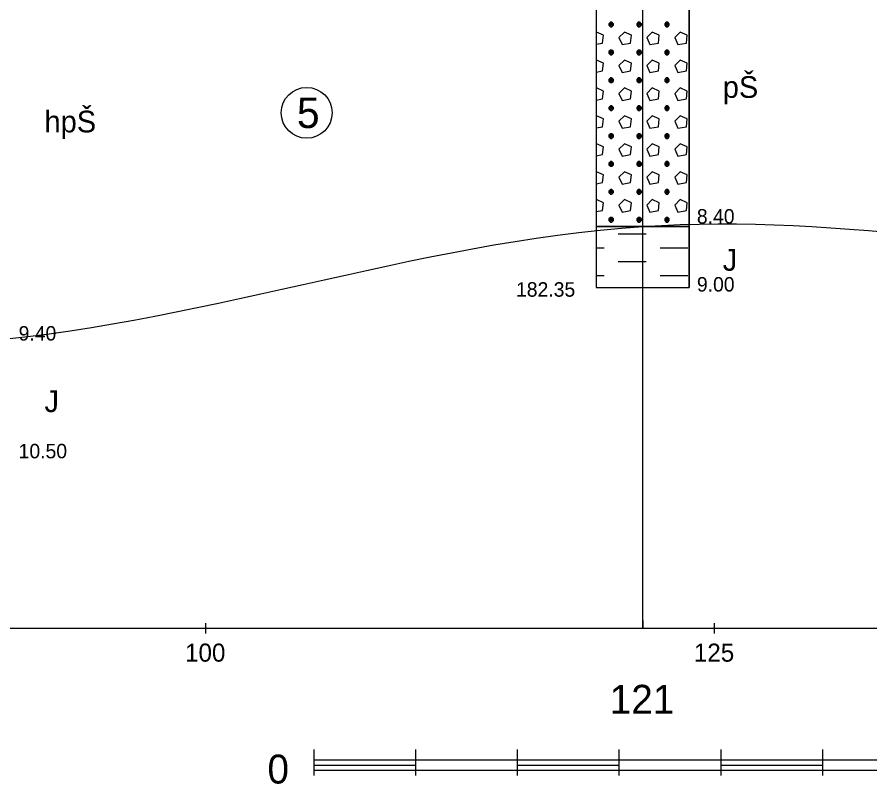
# Model space of a CAD drawing. Extents: x 3042 to 4120, y 576 to 2694.
# Drawn here: x 3345.86 to 3387.77, y 1544.18 to 1581.88 of the extents above; entities that cross this region are included whole.
import ezdxf

# ---------------------------------------------------------------- set-up
doc = ezdxf.new("R2010")
doc.units = 0
for name, color, linetype in [('14', 7, 'Continuous'), ('17', 7, 'Continuous'), ('18', 7, 'Continuous'), ('51', 7, 'Continuous'), ('52', 7, 'Continuous'), ('53', 7, 'Continuous'), ('56', 7, 'Continuous'), ('7', 7, 'Continuous'), ('8', 7, 'Continuous'), ('pomocna', 7, 'Continuous'), ('rozhraní', 7, 'Continuous')]:
    doc.layers.add(name, color=color, linetype=linetype)

msp = doc.modelspace()

# ---------------------------------------------------------------- linework, layer by layer
at = {"layer": '18'}
for p, q in [((3376.218, 1568.586), (3376.98, 1568.586)), ((3376.599, 1568.967), (3376.599, 1568.205)), ((3376.599, 1567.217), (3376.599, 1566.836)), ((3376.602, 1552.219), (3376.602, 1551.838))]:
    msp.add_line(p, q, dxfattribs=at)
at = {"layer": '51'}
for points in [[(3374.313, 1571.586), (3378.885, 1571.586), (3378.885, 1585.586), (3374.313, 1585.586)], [(3374.313, 1568.586), (3378.885, 1568.586), (3378.885, 1571.586), (3374.313, 1571.586)]]:
    msp.add_lwpolyline(points, close=True, dxfattribs=at)
for points in [[(3375.015, 1581.631), (3374.939, 1581.555), (3374.939, 1581.479), (3375.015, 1581.403), (3375.091, 1581.403), (3375.168, 1581.479), (3375.168, 1581.555), (3375.091, 1581.631), (3375.015, 1581.631), (3375.168, 1581.479), (3374.939, 1581.479), (3375.091, 1581.631)], [(3375.053, 1581.403), (3375.053, 1581.631)], [(3376.387, 1581.631), (3376.311, 1581.555), (3376.311, 1581.479), (3376.387, 1581.403), (3376.463, 1581.403), (3376.539, 1581.479), (3376.539, 1581.555), (3376.463, 1581.631), (3376.387, 1581.631), (3376.539, 1581.479), (3376.311, 1581.479), (3376.463, 1581.631)], [(3376.425, 1581.403), (3376.425, 1581.631)], [(3377.758, 1581.631), (3377.682, 1581.555), (3377.682, 1581.479), (3377.758, 1581.403), (3377.835, 1581.403), (3377.911, 1581.479), (3377.911, 1581.555), (3377.835, 1581.631), (3377.758, 1581.631), (3377.911, 1581.479), (3377.682, 1581.479), (3377.835, 1581.631)], [(3377.796, 1581.403), (3377.796, 1581.631)], [(3374.313, 1580.544), (3374.634, 1580.603), (3374.672, 1580.984), (3374.329, 1581.136), (3374.313, 1581.12)], [(3375.434, 1580.869), (3375.587, 1580.526), (3376.006, 1580.603), (3376.044, 1580.984), (3375.701, 1581.136), (3375.434, 1580.869)], [(3376.806, 1580.869), (3376.958, 1580.526), (3377.377, 1580.603), (3377.415, 1580.984), (3377.073, 1581.136), (3376.806, 1580.869)], [(3378.177, 1580.869), (3378.33, 1580.526), (3378.749, 1580.603), (3378.787, 1580.984), (3378.444, 1581.136), (3378.177, 1580.869)], [(3375.015, 1580.26), (3374.939, 1580.184), (3374.939, 1580.107), (3375.015, 1580.031), (3375.091, 1580.031), (3375.168, 1580.107), (3375.168, 1580.184), (3375.091, 1580.26), (3375.015, 1580.26), (3375.168, 1580.107), (3374.939, 1580.107), (3375.091, 1580.26)], [(3375.053, 1580.031), (3375.053, 1580.26)], [(3376.387, 1580.26), (3376.311, 1580.184), (3376.311, 1580.107), (3376.387, 1580.031), (3376.463, 1580.031), (3376.539, 1580.107), (3376.539, 1580.184), (3376.463, 1580.26), (3376.387, 1580.26), (3376.539, 1580.107), (3376.311, 1580.107), (3376.463, 1580.26)], [(3376.425, 1580.031), (3376.425, 1580.26)], [(3377.758, 1580.26), (3377.682, 1580.184), (3377.682, 1580.107), (3377.758, 1580.031), (3377.835, 1580.031), (3377.911, 1580.107), (3377.911, 1580.184), (3377.835, 1580.26), (3377.758, 1580.26), (3377.911, 1580.107), (3377.682, 1580.107), (3377.835, 1580.26)], [(3377.796, 1580.031), (3377.796, 1580.26)], [(3374.313, 1579.173), (3374.634, 1579.231), (3374.672, 1579.612), (3374.329, 1579.764), (3374.313, 1579.748)], [(3375.434, 1579.498), (3375.587, 1579.155), (3376.006, 1579.231), (3376.044, 1579.612), (3375.701, 1579.764), (3375.434, 1579.498)], [(3376.806, 1579.498), (3376.958, 1579.155), (3377.377, 1579.231), (3377.415, 1579.612), (3377.073, 1579.764), (3376.806, 1579.498)], [(3378.177, 1579.498), (3378.33, 1579.155), (3378.749, 1579.231), (3378.787, 1579.612), (3378.444, 1579.764), (3378.177, 1579.498)], [(3375.015, 1578.888), (3374.939, 1578.812), (3374.939, 1578.736), (3375.015, 1578.66), (3375.091, 1578.66), (3375.168, 1578.736), (3375.168, 1578.812), (3375.091, 1578.888), (3375.015, 1578.888), (3375.168, 1578.736), (3374.939, 1578.736), (3375.091, 1578.888)], [(3375.053, 1578.66), (3375.053, 1578.888)], [(3376.387, 1578.888), (3376.311, 1578.812), (3376.311, 1578.736), (3376.387, 1578.66), (3376.463, 1578.66), (3376.539, 1578.736), (3376.539, 1578.812), (3376.463, 1578.888), (3376.387, 1578.888), (3376.539, 1578.736), (3376.311, 1578.736), (3376.463, 1578.888)], [(3376.425, 1578.66), (3376.425, 1578.888)], [(3377.758, 1578.888), (3377.682, 1578.812), (3377.682, 1578.736), (3377.758, 1578.66), (3377.835, 1578.66), (3377.911, 1578.736), (3377.911, 1578.812), (3377.835, 1578.888), (3377.758, 1578.888), (3377.911, 1578.736), (3377.682, 1578.736), (3377.835, 1578.888)], [(3377.796, 1578.66), (3377.796, 1578.888)], [(3374.313, 1577.801), (3374.634, 1577.859), (3374.672, 1578.24), (3374.329, 1578.393), (3374.313, 1578.377)], [(3375.434, 1578.126), (3375.587, 1577.783), (3376.006, 1577.859), (3376.044, 1578.24), (3375.701, 1578.393), (3375.434, 1578.126)], [(3376.806, 1578.126), (3376.958, 1577.783), (3377.377, 1577.859), (3377.415, 1578.24), (3377.073, 1578.393), (3376.806, 1578.126)], [(3378.177, 1578.126), (3378.33, 1577.783), (3378.749, 1577.859), (3378.787, 1578.24), (3378.444, 1578.393), (3378.177, 1578.126)], [(3375.015, 1577.517), (3374.939, 1577.44), (3374.939, 1577.364), (3375.015, 1577.288), (3375.091, 1577.288), (3375.168, 1577.364), (3375.168, 1577.44), (3375.091, 1577.517), (3375.015, 1577.517), (3375.168, 1577.364), (3374.939, 1577.364), (3375.091, 1577.517)], [(3375.053, 1577.288), (3375.053, 1577.517)], [(3376.387, 1577.517), (3376.311, 1577.44), (3376.311, 1577.364), (3376.387, 1577.288), (3376.463, 1577.288), (3376.539, 1577.364), (3376.539, 1577.44), (3376.463, 1577.517), (3376.387, 1577.517), (3376.539, 1577.364), (3376.311, 1577.364), (3376.463, 1577.517)], [(3376.425, 1577.288), (3376.425, 1577.517)], [(3377.758, 1577.517), (3377.682, 1577.44), (3377.682, 1577.364), (3377.758, 1577.288), (3377.835, 1577.288), (3377.911, 1577.364), (3377.911, 1577.44), (3377.835, 1577.517), (3377.758, 1577.517), (3377.911, 1577.364), (3377.682, 1577.364), (3377.835, 1577.517)], [(3377.796, 1577.288), (3377.796, 1577.517)], [(3374.313, 1576.43), (3374.634, 1576.488), (3374.672, 1576.869), (3374.329, 1577.021), (3374.313, 1577.005)], [(3375.434, 1576.755), (3375.587, 1576.412), (3376.006, 1576.488), (3376.044, 1576.869), (3375.701, 1577.021), (3375.434, 1576.755)], [(3376.806, 1576.755), (3376.958, 1576.412), (3377.377, 1576.488), (3377.415, 1576.869), (3377.073, 1577.021), (3376.806, 1576.755)], [(3378.177, 1576.755), (3378.33, 1576.412), (3378.749, 1576.488), (3378.787, 1576.869), (3378.444, 1577.021), (3378.177, 1576.755)], [(3375.015, 1576.145), (3374.939, 1576.069), (3374.939, 1575.993), (3375.015, 1575.916), (3375.091, 1575.916), (3375.168, 1575.993), (3375.168, 1576.069), (3375.091, 1576.145), (3375.015, 1576.145), (3375.168, 1575.993), (3374.939, 1575.993), (3375.091, 1576.145)], [(3375.053, 1575.916), (3375.053, 1576.145)], [(3376.387, 1576.145), (3376.311, 1576.069), (3376.311, 1575.993), (3376.387, 1575.916), (3376.463, 1575.916), (3376.539, 1575.993), (3376.539, 1576.069), (3376.463, 1576.145), (3376.387, 1576.145), (3376.539, 1575.993), (3376.311, 1575.993), (3376.463, 1576.145)], [(3376.425, 1575.916), (3376.425, 1576.145)], [(3377.758, 1576.145), (3377.682, 1576.069), (3377.682, 1575.993), (3377.758, 1575.916), (3377.835, 1575.916), (3377.911, 1575.993), (3377.911, 1576.069), (3377.835, 1576.145), (3377.758, 1576.145), (3377.911, 1575.993), (3377.682, 1575.993), (3377.835, 1576.145)], [(3377.796, 1575.916), (3377.796, 1576.145)], [(3374.313, 1575.058), (3374.634, 1575.116), (3374.672, 1575.497), (3374.329, 1575.65), (3374.313, 1575.634)], [(3375.434, 1575.383), (3375.587, 1575.04), (3376.006, 1575.116), (3376.044, 1575.497), (3375.701, 1575.65), (3375.434, 1575.383)], [(3376.806, 1575.383), (3376.958, 1575.04), (3377.377, 1575.116), (3377.415, 1575.497), (3377.073, 1575.65), (3376.806, 1575.383)], [(3378.177, 1575.383), (3378.33, 1575.04), (3378.749, 1575.116), (3378.787, 1575.497), (3378.444, 1575.65), (3378.177, 1575.383)], [(3375.015, 1574.773), (3374.939, 1574.697), (3374.939, 1574.621), (3375.015, 1574.545), (3375.091, 1574.545), (3375.168, 1574.621), (3375.168, 1574.697), (3375.091, 1574.773), (3375.015, 1574.773), (3375.168, 1574.621), (3374.939, 1574.621), (3375.091, 1574.773)], [(3375.053, 1574.545), (3375.053, 1574.773)], [(3376.387, 1574.773), (3376.311, 1574.697), (3376.311, 1574.621), (3376.387, 1574.545), (3376.463, 1574.545), (3376.539, 1574.621), (3376.539, 1574.697), (3376.463, 1574.773), (3376.387, 1574.773), (3376.539, 1574.621), (3376.311, 1574.621), (3376.463, 1574.773)], [(3376.425, 1574.545), (3376.425, 1574.773)], [(3377.758, 1574.773), (3377.682, 1574.697), (3377.682, 1574.621), (3377.758, 1574.545), (3377.835, 1574.545), (3377.911, 1574.621), (3377.911, 1574.697), (3377.835, 1574.773), (3377.758, 1574.773), (3377.911, 1574.621), (3377.682, 1574.621), (3377.835, 1574.773)], [(3377.796, 1574.545), (3377.796, 1574.773)], [(3374.313, 1573.686), (3374.634, 1573.745), (3374.672, 1574.126), (3374.329, 1574.278), (3374.313, 1574.262)], [(3375.434, 1574.011), (3375.587, 1573.668), (3376.006, 1573.745), (3376.044, 1574.126), (3375.701, 1574.278), (3375.434, 1574.011)], [(3376.806, 1574.011), (3376.958, 1573.668), (3377.377, 1573.745), (3377.415, 1574.126), (3377.073, 1574.278), (3376.806, 1574.011)], [(3378.177, 1574.011), (3378.33, 1573.668), (3378.749, 1573.745), (3378.787, 1574.126), (3378.444, 1574.278), (3378.177, 1574.011)], [(3375.015, 1573.402), (3374.939, 1573.326), (3374.939, 1573.249), (3375.015, 1573.173), (3375.091, 1573.173), (3375.168, 1573.249), (3375.168, 1573.326), (3375.091, 1573.402), (3375.015, 1573.402), (3375.168, 1573.249), (3374.939, 1573.249), (3375.091, 1573.402)], [(3375.053, 1573.173), (3375.053, 1573.402)], [(3376.387, 1573.402), (3376.311, 1573.326), (3376.311, 1573.249), (3376.387, 1573.173), (3376.463, 1573.173), (3376.539, 1573.249), (3376.539, 1573.326), (3376.463, 1573.402), (3376.387, 1573.402), (3376.539, 1573.249), (3376.311, 1573.249), (3376.463, 1573.402)], [(3376.425, 1573.173), (3376.425, 1573.402)], [(3377.758, 1573.402), (3377.682, 1573.326), (3377.682, 1573.249), (3377.758, 1573.173), (3377.835, 1573.173), (3377.911, 1573.249), (3377.911, 1573.326), (3377.835, 1573.402), (3377.758, 1573.402), (3377.911, 1573.249), (3377.682, 1573.249), (3377.835, 1573.402)], [(3377.796, 1573.173), (3377.796, 1573.402)], [(3374.313, 1572.315), (3374.634, 1572.373), (3374.672, 1572.754), (3374.329, 1572.906), (3374.313, 1572.89)], [(3375.434, 1572.64), (3375.587, 1572.297), (3376.006, 1572.373), (3376.044, 1572.754), (3375.701, 1572.906), (3375.434, 1572.64)], [(3376.806, 1572.64), (3376.958, 1572.297), (3377.377, 1572.373), (3377.415, 1572.754), (3377.073, 1572.906), (3376.806, 1572.64)], [(3378.177, 1572.64), (3378.33, 1572.297), (3378.749, 1572.373), (3378.787, 1572.754), (3378.444, 1572.906), (3378.177, 1572.64)], [(3375.015, 1572.03), (3374.939, 1571.954), (3374.939, 1571.878), (3375.015, 1571.802), (3375.091, 1571.802), (3375.168, 1571.878), (3375.168, 1571.954), (3375.091, 1572.03), (3375.015, 1572.03), (3375.168, 1571.878), (3374.939, 1571.878), (3375.091, 1572.03)], [(3375.053, 1571.802), (3375.053, 1572.03)], [(3376.387, 1572.03), (3376.311, 1571.954), (3376.311, 1571.878), (3376.387, 1571.802), (3376.463, 1571.802), (3376.539, 1571.878), (3376.539, 1571.954), (3376.463, 1572.03), (3376.387, 1572.03), (3376.539, 1571.878), (3376.311, 1571.878), (3376.463, 1572.03)], [(3376.425, 1571.802), (3376.425, 1572.03)], [(3377.758, 1572.03), (3377.682, 1571.954), (3377.682, 1571.878), (3377.758, 1571.802), (3377.835, 1571.802), (3377.911, 1571.878), (3377.911, 1571.954), (3377.835, 1572.03), (3377.758, 1572.03), (3377.911, 1571.878), (3377.682, 1571.878), (3377.835, 1572.03)], [(3377.796, 1571.802), (3377.796, 1572.03)], [(3375.396, 1571.23), (3376.082, 1571.23)], [(3376.082, 1571.23), (3376.768, 1571.23)], [(3374.313, 1570.544), (3374.71, 1570.544)], [(3377.454, 1570.544), (3378.139, 1570.544)], [(3378.139, 1570.544), (3378.825, 1570.544)], [(3375.396, 1569.858), (3376.082, 1569.858)], [(3376.082, 1569.858), (3376.768, 1569.858)], [(3374.313, 1569.173), (3374.71, 1569.173)], [(3377.454, 1569.173), (3378.139, 1569.173)], [(3378.139, 1569.173), (3378.825, 1569.173)]]:
    msp.add_lwpolyline(points, dxfattribs=at)
at = {"layer": '53'}
for points in [[(3374.313, 1613.586), (3374.313, 1568.586)], [(3378.885, 1613.586), (3378.885, 1568.586)], [(3374.313, 1571.586), (3378.885, 1571.586)], [(3374.313, 1568.586), (3378.885, 1568.586)]]:
    msp.add_lwpolyline(points, dxfattribs=at)
at = {"layer": '56'}
for points in [[(3376.599, 1571.967), (3376.599, 1571.205)], [(3376.218, 1571.586), (3376.98, 1571.586)], [(3376.218, 1568.586), (3376.98, 1568.586)], [(3376.599, 1568.967), (3376.599, 1568.205)]]:
    msp.add_lwpolyline(points, dxfattribs=at)
at = {"layer": '7'}
for p, q in [((3255.132, 1551.838), (3515.772, 1551.838)), ((3355.132, 1551.584), (3355.132, 1552.092)), ((3380.132, 1551.584), (3380.132, 1552.092))]:
    msp.add_line(p, q, dxfattribs=at)
at = {"layer": '8'}
for p, q in [((3360.452, 1544.599), (3360.452, 1545.869)), ((3365.452, 1544.599), (3365.452, 1545.869)), ((3370.452, 1544.599), (3370.452, 1545.869)), ((3375.452, 1544.599), (3375.452, 1545.869)), ((3380.452, 1544.599), (3380.452, 1545.869)), ((3385.452, 1544.599), (3385.452, 1545.869)), ((3360.452, 1545.361), (3410.452, 1545.361)), ((3360.452, 1545.107), (3365.452, 1545.107)), ((3370.452, 1545.107), (3375.452, 1545.107)), ((3380.452, 1545.107), (3385.452, 1545.107)), ((3360.452, 1544.853), (3410.452, 1544.853))]:
    msp.add_line(p, q, dxfattribs=at)
at = {"layer": 'pomocna'}
msp.add_line((3376.602, 1551.838), (3376.602, 1611.375), dxfattribs=at)
at = {"layer": 'rozhraní'}
msp.add_circle((3360.093, 1577.175), 1.25, dxfattribs=at)
msp.add_spline([(3259.44, 1578.878), (3265.132, 1578.438), (3304.222, 1572.038), (3343.272, 1565.888), (3376.602, 1571.588), (3406.282, 1569.388), (3454.612, 1572.038), (3505.772, 1575.788), (3516.375, 1575.788)], degree=3, dxfattribs=at)

# ---------------------------------------------------------------- texts
at = {"layer": '14'}
msp.add_text('121', height=1.4224, dxfattribs=at).set_placement((3374.982, 1547.632))
at = {"layer": '17'}
for p in [(3370.376, 1568.134), (3370.379, 1568.136)]:
    msp.add_text('182.35', height=0.7112, dxfattribs=at).set_placement(p)
at = {"layer": '52'}
for s, height, p in [('pŠ', 1.0668, (3380.536, 1577.908)), ('hpŠ', 1.0668, (3347.209, 1576.21)), ('8.40', 0.7112, (3379.266, 1571.729)), ('J', 1.067, (3380.536, 1569.408)), ('9.00', 0.7112, (3379.266, 1568.388)), ('9.40', 0.7112, (3345.939, 1565.978)), ('J', 1.067, (3347.209, 1562.46)), ('10.50', 0.7112, (3345.939, 1560.19))]:
    msp.add_text(s, height=height, dxfattribs=at).set_placement(p)
at = {"layer": '7'}
for s, p in [('100', (3354.116, 1550.194)), ('125', (3379.116, 1550.194))]:
    msp.add_text(s, height=0.889, dxfattribs=at).set_placement(p)
at = {"layer": '8'}
msp.add_text('0', height=1.422, dxfattribs=at).set_placement((3358.166, 1544.203))
at = {"layer": 'rozhraní'}
msp.add_text('5', height=1.5, dxfattribs=at).set_placement((3359.612, 1576.425))

doc.saveas('drawing.dxf')
